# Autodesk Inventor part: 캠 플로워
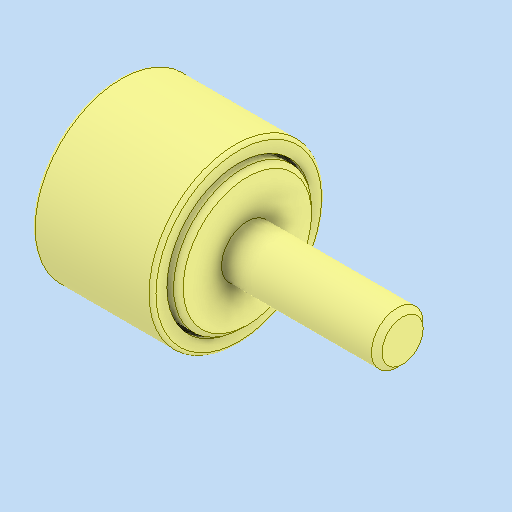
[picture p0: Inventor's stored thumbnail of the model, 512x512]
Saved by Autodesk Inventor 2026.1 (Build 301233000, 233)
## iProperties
Created: 2025-09
Part Number: 캠 플로워
Material: 일반
Description: Cam Follower with a Hexagon Socket Model CF-A-
Document SubType Name: Modeling
Designer: PC-30
Density: 1 g/cm^3
Appearance: 기본값
Company: THK
Author: jhkim
Sending System: Autodesk Inventor 2026
Preprocessor: ST-DEVELOPER v20.1
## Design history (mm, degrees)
feature "Solid1"
node "솔리드1"
